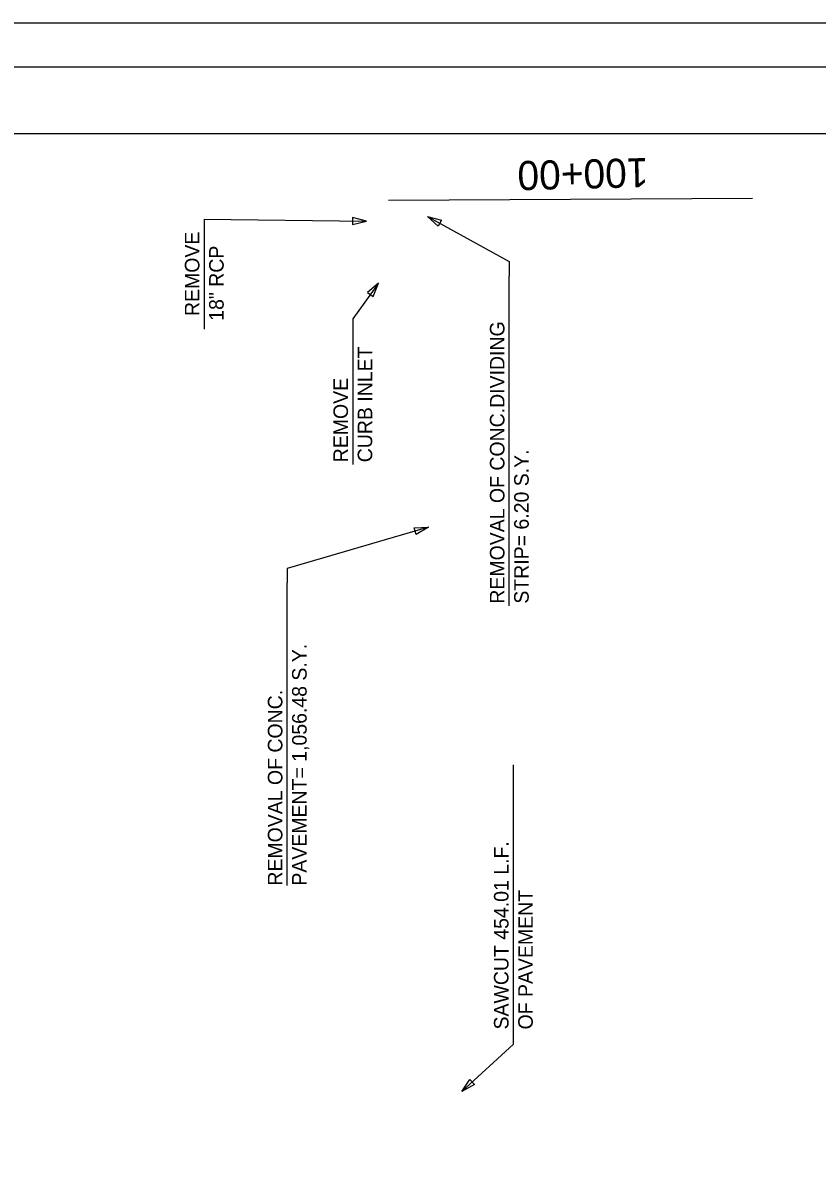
# Model space of a CAD drawing. Extents: x 2150259 to 2151459, y 143090 to 145092.
# Drawn here: x 2150586.7 to 2150914.2, y 144624.4 to 145092 of the extents above; entities that cross this region are included whole.
import ezdxf

# ---------------------------------------------------------------- set-up
doc = ezdxf.new("R2010")
doc.units = 0
for name, color, linetype in [('PR_Removal_Txt', 7, 'Continuous'), ('PR_Txt', 7, 'Continuous'), ('SHT_Match_Lines', 7, 'Continuous'), ('SHT_Plot_Shape_Full', 7, 'Continuous'), ('SHT_Plot_Shape_Half', 7, 'Continuous'), ('SHT_Sheet_Border', 7, 'Continuous')]:
    doc.layers.add(name, color=color, linetype=linetype)

msp = doc.modelspace()

# ---------------------------------------------------------------- linework, layer by layer
at = {"layer": 'PR_Removal_Txt'}
for p, q in [((2150661.57, 145011.09), (2150661.57, 144965.69)), ((2150661.57, 145011.09), (2150728.49, 145010.25)), ((2150787.3, 144851.72), (2150787.3, 144987.64)), ((2150722.8, 144963.92), (2150722.8, 144909.92)), ((2150695.77, 144736.37), (2150695.77, 144861.13)), ((2150788.97, 144677.09), (2150788.97, 144786.17))]:
    msp.add_line(p, q, dxfattribs=at)
for points in [[(2150728.49, 145010.25), (2150722.69, 145011.78), (2150722.65, 145008.87)], [(2150753.58, 145012.21), (2150759.38, 145010.67), (2150757.98, 145008.13)], [(2150733.44, 144984.75), (2150728.87, 144980.86), (2150731.24, 144979.17)], [(2150754.02, 144884.06), (2150748.84, 144881.04), (2150748.03, 144883.83)], [(2150767.73, 144651.46), (2150771.02, 144656.48), (2150773, 144654.35)]]:
    msp.add_lwpolyline(points, close=True, dxfattribs=at)
for points in [[(2150753.58, 145012.21), (2150787.3, 144993.64), (2150787.3, 144987.64)], [(2150733.44, 144984.75), (2150722.8, 144969.92), (2150722.8, 144963.92)], [(2150754.02, 144884.06), (2150695.77, 144867.13), (2150695.77, 144861.13)], [(2150767.73, 144651.46), (2150788.97, 144671.09), (2150788.97, 144677.09)]]:
    msp.add_lwpolyline(points, dxfattribs=at)
at = {"layer": 'SHT_Match_Lines'}
msp.add_line((2150887.52, 145019.63), (2150737.53, 145018.72), dxfattribs=at)
at = {"layer": 'SHT_Plot_Shape_Full'}
msp.add_lwpolyline([(2150259.22, 143292.05), (2150259.22, 145092.05), (2151459.22, 145092.05), (2151459.22, 143292.05)], close=True, dxfattribs=at)
at = {"layer": 'SHT_Plot_Shape_Half'}
msp.add_lwpolyline([(2150300.47, 143373.92), (2150300.47, 145073.92), (2151400.47, 145073.92), (2151400.47, 143373.92)], close=True, dxfattribs=at)
at = {"layer": 'SHT_Sheet_Border'}
msp.add_lwpolyline([(2151375.47, 145046.42), (2151375.47, 143471.42), (2150325.47, 143471.42), (2150325.47, 145046.42)], close=True, dxfattribs=at)

# ---------------------------------------------------------------- texts
at = {"layer": 'PR_Removal_Txt'}
for s, p in [('REMOVE', (2150659.57, 144971.15)), ('18" RCP', (2150669.57, 144969.2)), ('REMOVAL OF CONC.DIVIDING', (2150785.3, 144852.59)), ('CURB INLET', (2150730.8, 144910.87)), ('REMOVE', (2150720.8, 144910.87)), ('STRIP= 6.20 S.Y.', (2150795.3, 144852.59)), ('PAVEMENT= 1,056.48 S.Y.', (2150703.77, 144736.37)), ('REMOVAL OF CONC.', (2150693.77, 144736.37)), ('SAWCUT 454.01 L.F. ', (2150786.97, 144677.09)), ('OF PAVEMENT', (2150796.97, 144677.09))]:
    msp.add_text(s, height=6, rotation=90, dxfattribs=at).set_placement(p)
at = {"layer": 'PR_Txt'}
msp.add_text('100+00', height=12, rotation=181.4099, dxfattribs=at).set_placement((2150844.47, 145036.31))

doc.saveas('drawing.dxf')
